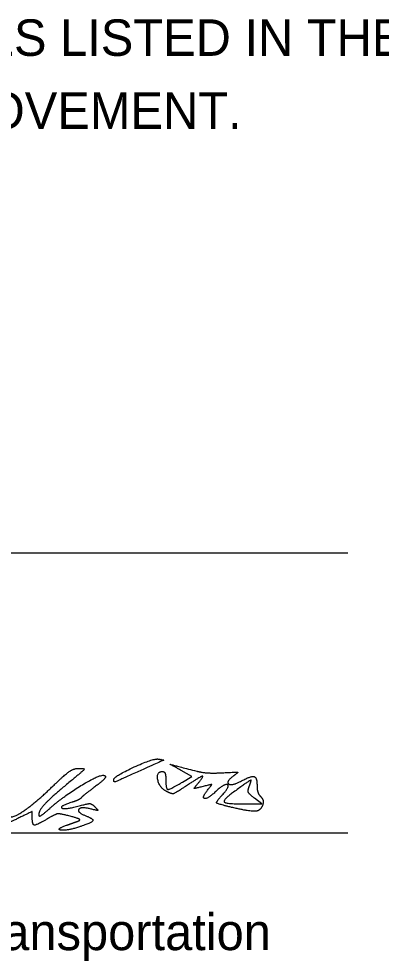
# Model space of a CAD drawing. Extents: x 43.1 to 77.1, y 2.7 to 24.7.
# Drawn here: x 69.896 to 71.287, y 9.959 to 13.574 of the extents above; entities that cross this region are included whole.
import ezdxf

# ---------------------------------------------------------------- set-up
doc = ezdxf.new("R2010")
doc.units = 0
doc.layers.add('SH_Data', color=7, linetype='Continuous')
doc.layers.add('SH_Text', color=7, linetype='Continuous')

msp = doc.modelspace()

# ---------------------------------------------------------------- linework, layer by layer
at = {"layer": 'SH_Data'}
for p, q in [((67.6588, 11.5259), (71.1588, 11.5259)), ((67.6588, 10.4508), (71.1588, 10.4508))]:
    msp.add_line(p, q, dxfattribs=at)
at = {"layer": 'SH_Text'}
for p, q in [((70.2604, 10.655), (70.2604, 10.655)), ((70.7129, 10.5487), (70.7129, 10.5487))]:
    msp.add_line(p, q, dxfattribs=at)
for points in [[(70.5242, 10.6454), (70.5606, 10.6669), (70.5199, 10.6899)], [(70.7729, 10.5619), (70.8291, 10.562), (70.8004, 10.5841)]]:
    msp.add_lwpolyline(points, dxfattribs=at)
for points in [[(70.2604, 10.655), (70.2604, 10.6674), (70.4132, 10.7377), (70.4321, 10.734)], [(70.4321, 10.734), (70.4528, 10.73), (70.4535, 10.7304), (70.3319, 10.6757)], [(70.5199, 10.6899), (70.477, 10.714), (70.4761, 10.714), (70.5791, 10.6876)], [(70.0073, 10.538), (70.0609, 10.5868), (70.2078, 10.6769), (70.2247, 10.6712)], [(70.026, 10.6292), (70.0712, 10.673), (70.1084, 10.6987), (70.126, 10.6984)], [(70.126, 10.6984), (70.1503, 10.6979), (70.1465, 10.6915), (70.0979, 10.6515)], [(70.2247, 10.6712), (70.2331, 10.6684), (70.2179, 10.6497), (70.1908, 10.6295)], [(70.3319, 10.6757), (70.2694, 10.6476), (70.2604, 10.645), (70.2604, 10.655)], [(70.4614, 10.6109), (70.4349, 10.625), (70.4239, 10.6864), (70.4479, 10.6864)], [(70.4479, 10.6864), (70.4548, 10.6864), (70.4604, 10.6724), (70.4604, 10.6552)], [(70.5838, 10.6406), (70.6082, 10.6702), (70.5924, 10.6664), (70.5361, 10.6292)], [(70.5791, 10.6876), (70.5998, 10.6823), (70.6448, 10.6796), (70.6791, 10.6815)], [(70.6791, 10.6815), (70.734, 10.6846), (70.7389, 10.683), (70.719, 10.6682)], [(70.719, 10.6682), (70.6902, 10.6467), (70.7131, 10.6303), (70.7468, 10.6483)], [(70.7468, 10.6483), (70.787, 10.6699), (70.8104, 10.6641), (70.8104, 10.6327)], [(70.0979, 10.6515), (70.0239, 10.5905), (69.9729, 10.537), (69.9729, 10.5203)], [(70.4604, 10.6552), (70.4604, 10.6184), (70.4747, 10.6162), (70.5242, 10.6454)], [(70.6032, 10.6289), (70.5701, 10.6206), (70.5683, 10.6218), (70.5838, 10.6406)], [(70.6233, 10.6182), (70.6379, 10.6357), (70.6356, 10.637), (70.6032, 10.6289)], [(70.6772, 10.5967), (70.7076, 10.6304), (70.686, 10.6413), (70.652, 10.6094)], [(70.7806, 10.6296), (70.7905, 10.6554), (70.7823, 10.6523), (70.7197, 10.6067)], [(70.8104, 10.6327), (70.8104, 10.6169), (70.8168, 10.5975), (70.8245, 10.5898)], [(69.8604, 10.5224), (69.8604, 10.4996), (69.9557, 10.561), (70.026, 10.6292)], [(70.1908, 10.6295), (70.1637, 10.6093), (70.1388, 10.5893), (70.1354, 10.585)], [(70.5361, 10.6292), (70.4961, 10.6027), (70.4828, 10.5994), (70.4614, 10.6109)], [(70.652, 10.6094), (70.6201, 10.5794), (70.597, 10.5865), (70.6233, 10.6182)], [(70.7129, 10.5487), (70.6581, 10.5617), (70.6524, 10.5694), (70.6772, 10.5967)], [(70.7197, 10.6067), (70.677, 10.5756), (70.6935, 10.5618), (70.7729, 10.5619)], [(70.8004, 10.5841), (70.78, 10.5998), (70.7743, 10.613), (70.7806, 10.6296)], [(70.101, 10.5685), (70.0515, 10.5531), (70.071, 10.5394), (70.1228, 10.5532)], [(70.1354, 10.585), (70.1319, 10.5808), (70.1165, 10.5733), (70.101, 10.5685)], [(70.1228, 10.5532), (70.1612, 10.5635), (70.1764, 10.5628), (70.1884, 10.5506)], [(70.8245, 10.5898), (70.8323, 10.582), (70.8353, 10.5668), (70.8312, 10.556)], [(69.9479, 10.5099), (69.9479, 10.5327), (69.9468, 10.5327), (69.9007, 10.5099)], [(69.9729, 10.5203), (69.9729, 10.5128), (69.9884, 10.5208), (70.0073, 10.538)], [(70.093, 10.5148), (70.0542, 10.5247), (70.0374, 10.5231), (70.0098, 10.5068)], [(70.1698, 10.5431), (70.133, 10.5522), (70.1198, 10.5291), (70.1541, 10.5159)], [(70.1884, 10.5506), (70.2011, 10.5377), (70.1975, 10.5363), (70.1698, 10.5431)], [(70.8312, 10.556), (70.8231, 10.5349), (70.7819, 10.5324), (70.7129, 10.5487)], [(69.9007, 10.5099), (69.8633, 10.4914), (69.8447, 10.4891), (69.8116, 10.4986)], [(70.0098, 10.5068), (69.9648, 10.4802), (69.9479, 10.481), (69.9479, 10.5099)], [(70.0791, 10.4799), (70.0929, 10.4848), (70.1126, 10.4919), (70.1229, 10.4956)], [(70.1229, 10.4956), (70.1343, 10.4998), (70.1226, 10.5073), (70.093, 10.5148)], [(70.1541, 10.5159), (70.1847, 10.5042), (70.1758, 10.4893), (70.129, 10.4739)], [(70.129, 10.4739), (70.0824, 10.4585), (70.0351, 10.4642), (70.0791, 10.4799)]]:
    msp.add_open_spline(points, degree=2, dxfattribs=at)

# ---------------------------------------------------------------- texts
for s, p in [('PLANS AND CHANGES LISTED IN THE PROPOSAL SHALL', (67.9636, 13.4324)), ('GOVERN THIS IMPROVEMENT.', (67.9636, 13.1524)), ('Director, Department of Transportation', (67.6588, 10.0008))]:
    msp.add_text(s, height=0.14, dxfattribs=at).set_placement(p)

doc.saveas('drawing.dxf')
